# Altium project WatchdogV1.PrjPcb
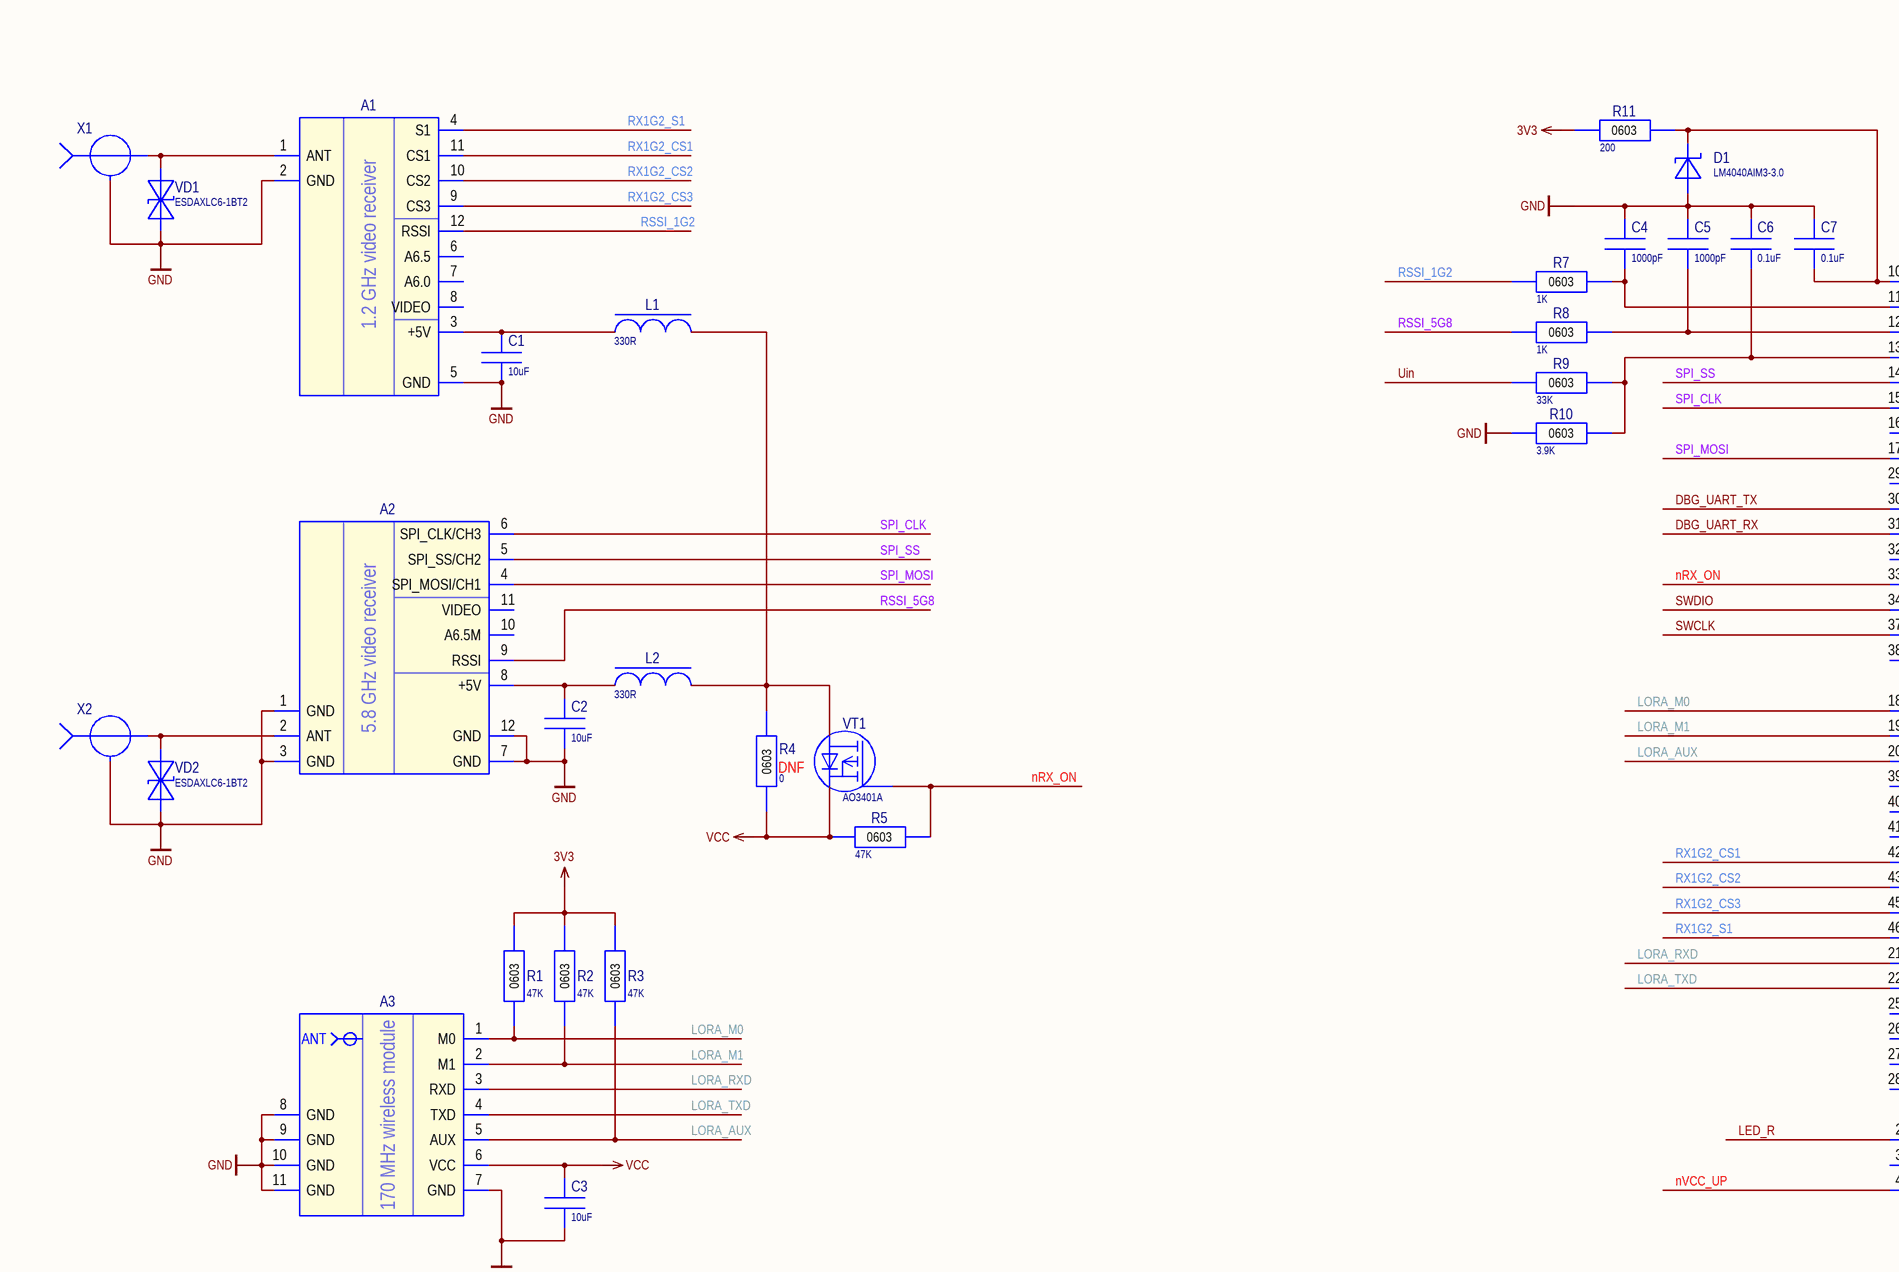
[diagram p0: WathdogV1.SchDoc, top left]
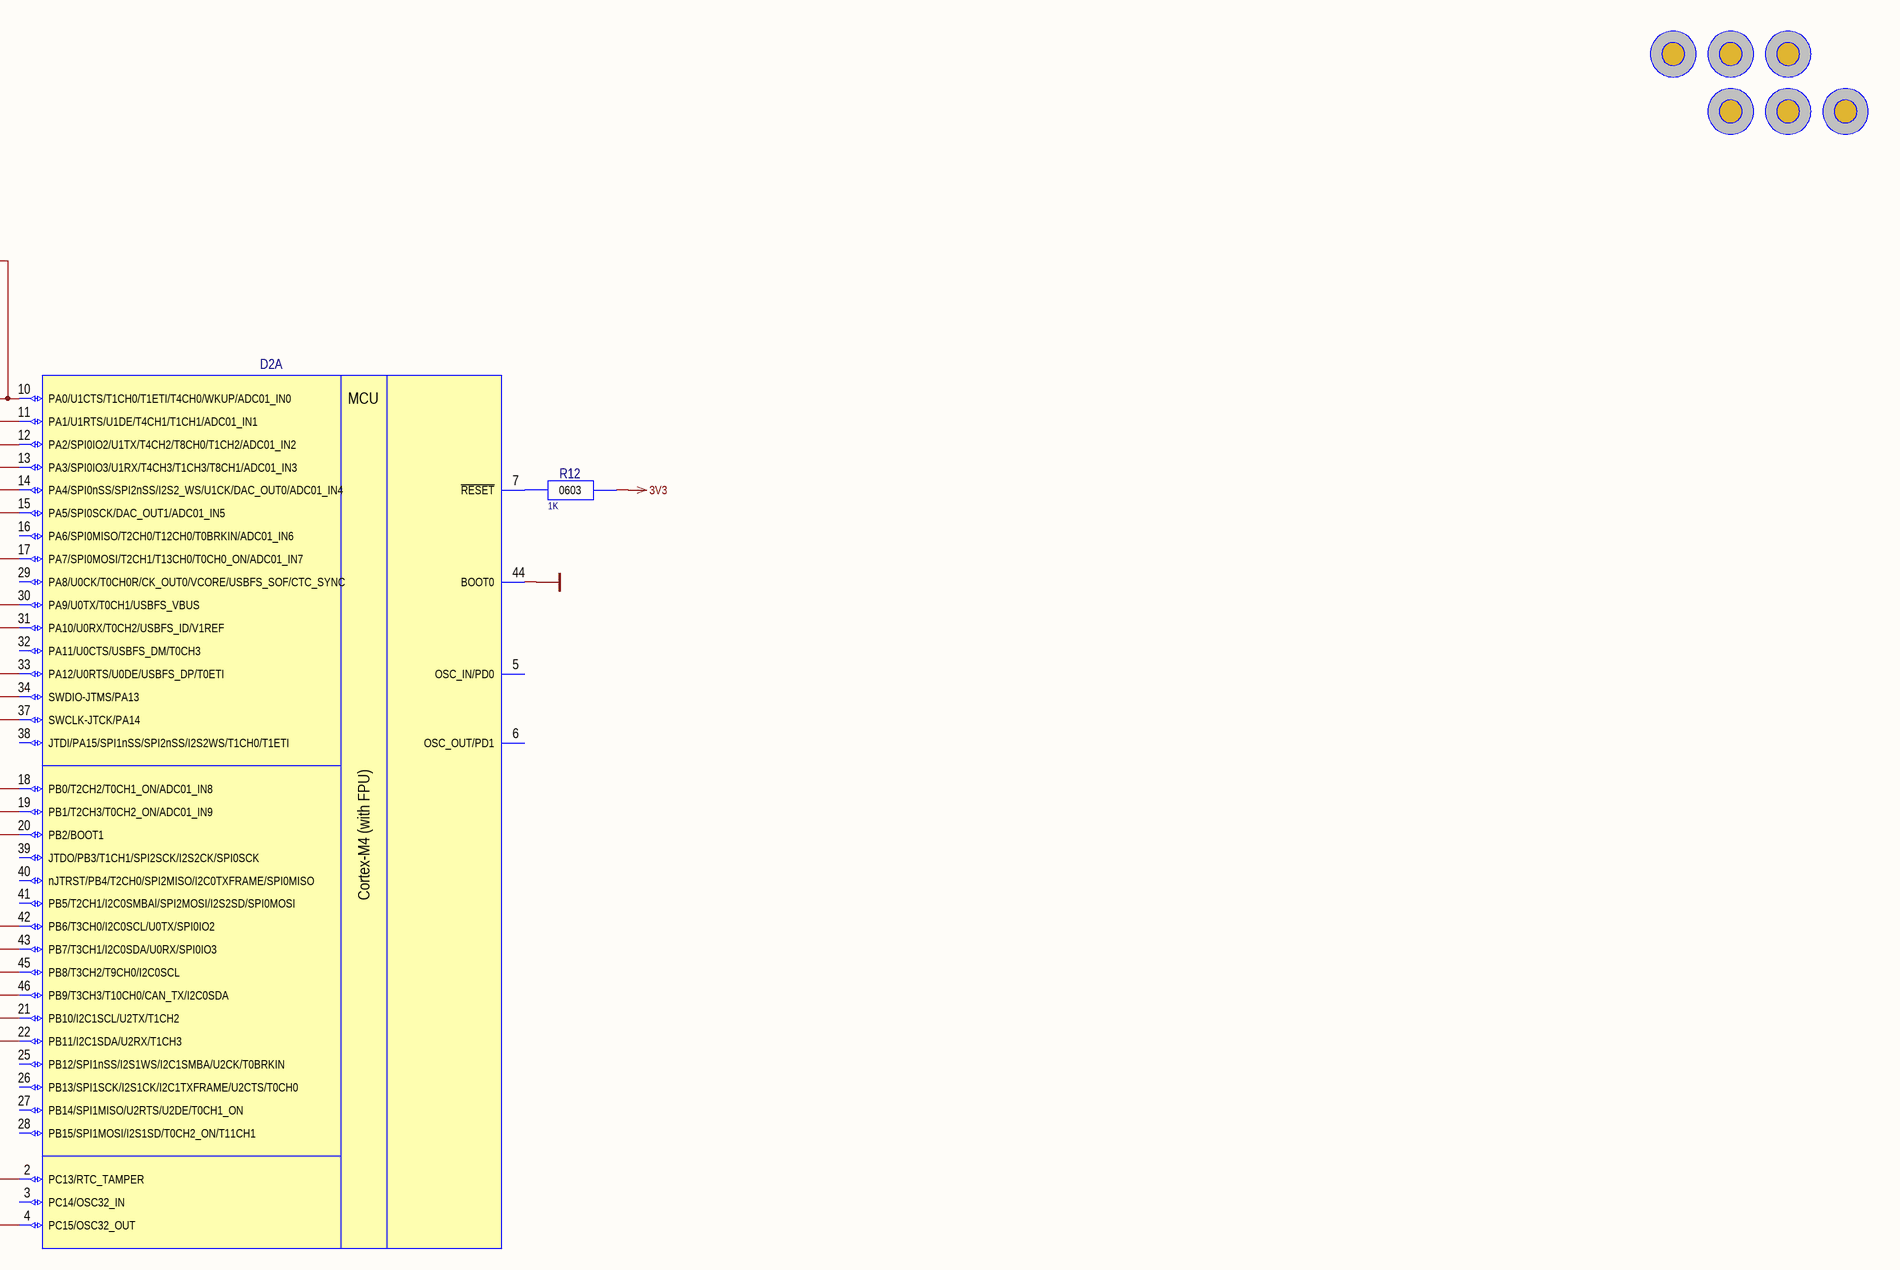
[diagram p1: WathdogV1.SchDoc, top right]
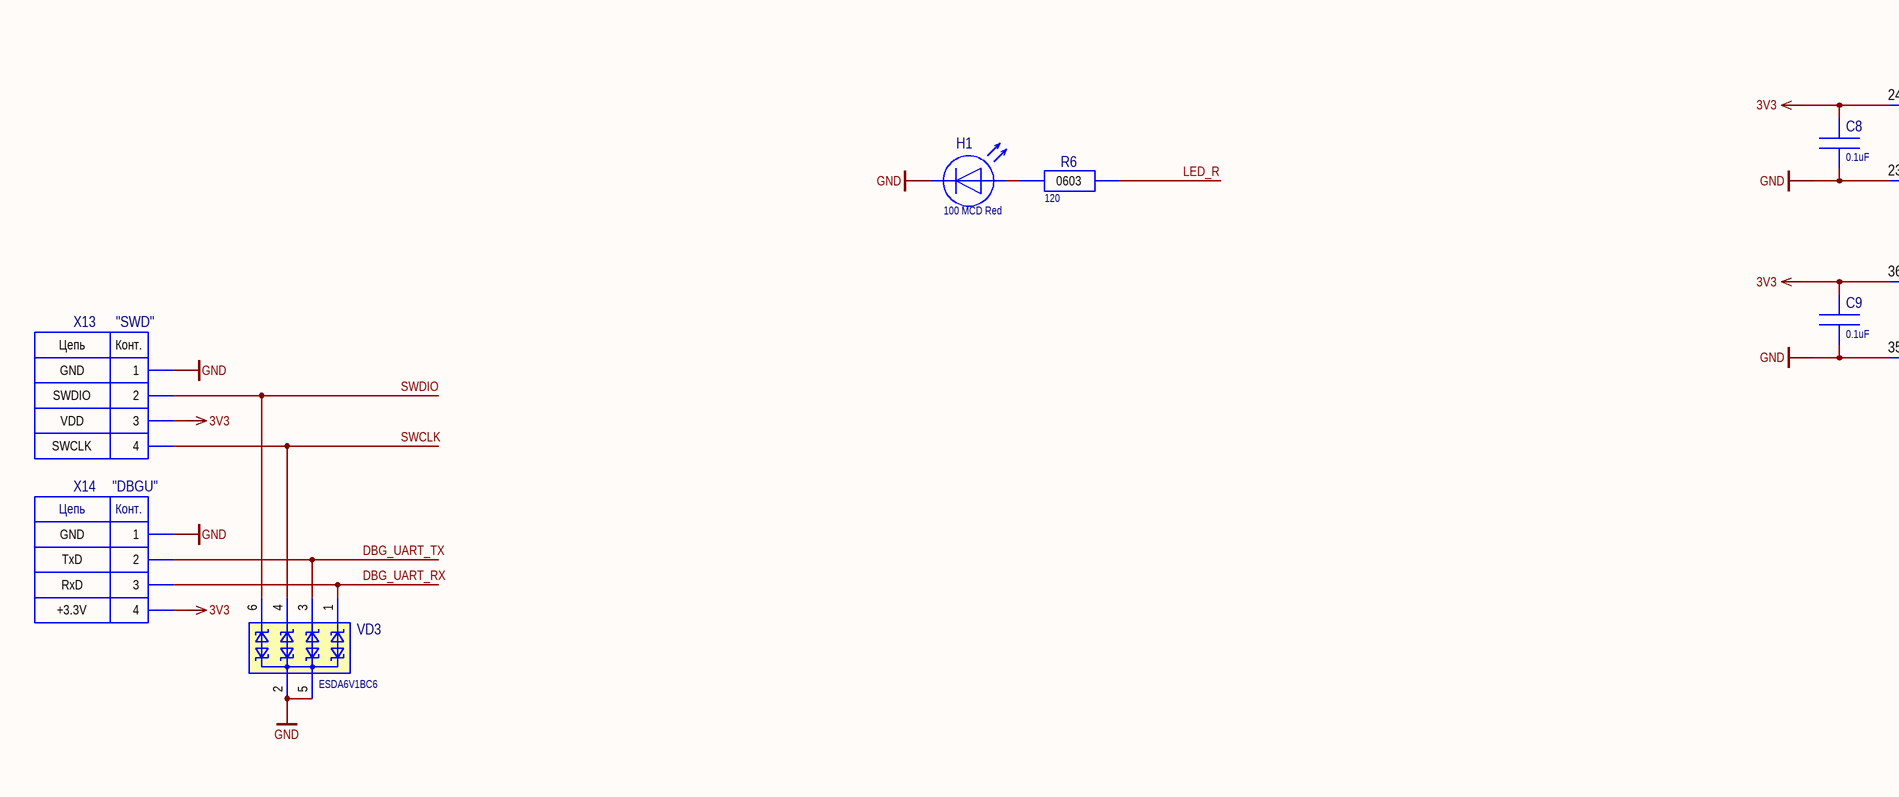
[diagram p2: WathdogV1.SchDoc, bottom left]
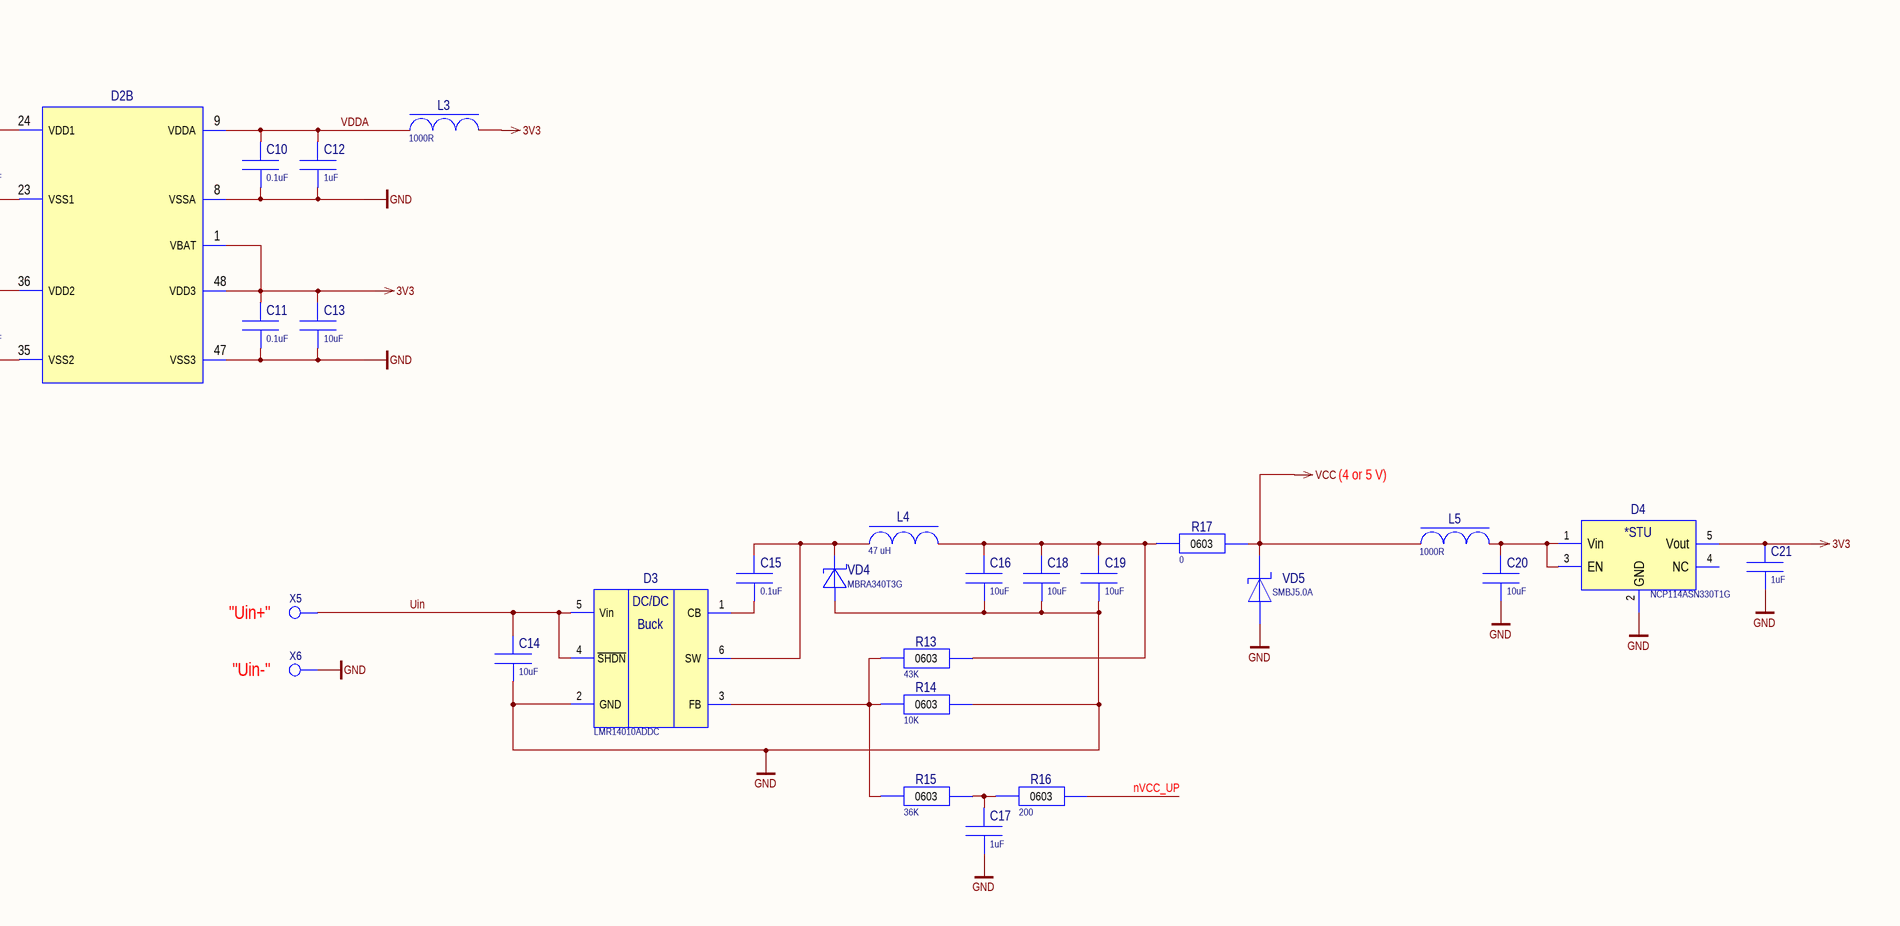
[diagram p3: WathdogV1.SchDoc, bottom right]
1 sheet, 69 parts. Net scope: global (net labels, ports and power ports of the same name join across sheets).
Board file: WatchdogV1.PcbDoc

## Sheet WathdogV1.SchDoc
size 840 x 594 mm; SheetNumber: 1; SheetTotal: 1; Разработал: КБИ

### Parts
A1  Receiver SM1370R  [SM1370R]  (value not drawn)
A2  Receiver RX5808  [RX5808]  (value not drawn)
A3  Wireless Module E32-170T30D  [E32-170T30D]  (value not drawn)
C1  value 10uF  [CC1206]  (hidden comment: Конденсатор керамический 1206-X7R-25V-10uF±10%)
C2  value 10uF  [CC1206]  (hidden comment: Конденсатор керамический 1206-X7R-25V-10uF±10%)
C3  value 10uF  [CC1206]  (hidden comment: Конденсатор керамический 1206-X7R-25V-10uF±10%)
C4  value 1000pF  [CC0603]  (hidden comment: Конденсатор керамический 0603-NP0-50V-1000pF±5%)
C5  value 1000pF  [CC0603]  (hidden comment: Конденсатор керамический 0603-NP0-50V-1000pF±5%)
C6  value 0.1uF  [CC0603]  (hidden comment: Конденсатор керамический 0603-X7R-50V-0.1uF±10%)
C7  value 0.1uF  [CC0603]  (hidden comment: Конденсатор керамический 0603-X7R-50V-0.1uF±10%)
C8  value 0.1uF  [CC0603]  (hidden comment: Конденсатор керамический 0603-X7R-50V-0.1uF±10%)
C9  value 0.1uF  [CC0603]  (hidden comment: Конденсатор керамический 0603-X7R-50V-0.1uF±10%)
C10  value 0.1uF  [CC0603]  (hidden comment: Конденсатор керамический 0603-X7R-50V-0.1uF±10%)
C11  value 0.1uF  [CC0603]  (hidden comment: Конденсатор керамический 0603-X7R-50V-0.1uF±10%)
C12  value 1uF  [CC0603]  (hidden comment: Конденсатор керамический 0603-X7R-16V-1uF±20%)
C13  value 10uF  [CC1206]  (hidden comment: Конденсатор керамический 1206-X7R-25V-10uF±10%)
C14  value 10uF  [CC1210]  (hidden comment: Конденсатор керамический 1210-X7R-63V-10uF±10%)
C15  value 0.1uF  [CC0603]  (hidden comment: Конденсатор керамический 0603-X7R-50V-0.1uF±10%)
C16  value 10uF  [CC1206]  (hidden comment: Конденсатор керамический 1206-X7R-25V-10uF±10%)
C17  value 1uF  [CC0603]  (hidden comment: Конденсатор керамический 0603-X7R-16V-1uF±20%)
C18  value 10uF  [CC1206]  (hidden comment: Конденсатор керамический 1206-X7R-25V-10uF±10%)
C19  value 10uF  [CC1206]  (hidden comment: Конденсатор керамический 1206-X7R-25V-10uF±10%)
C20  value 10uF  [CC1206]  (hidden comment: Конденсатор керамический 1206-X7R-25V-10uF±10%)
C21  value 1uF  [CC0603]  (hidden comment: Конденсатор керамический 0603-X7R-16V-1uF±20%)
D1  Микросхема LM4040AIM3-3.0  [SOT-23]  (value not drawn)
D2  Микросхема GD32E103CBT6  [LQFP48_7x7]  (value not drawn)  (parts A,B of 2)
D3  Микросхема LMR14010ADDC  [SOT-23-6]  (value not drawn)
D4  Name: NCP114ASN330T1G  [TSOP-5]  (hidden comment: Микросхема NCP114ASN330T1G)
H1  value 100 MCD Red  [LED0603_Red]  (hidden comment: Светодиод 0603-RED-[100-150]MCD)
L1  value 330R  [CL0603]  (hidden comment: Дроссель BLM18PG331SN1D)
L2  value 330R  [CL0603]  (hidden comment: Дроссель BLM18PG331SN1D)
L3  value 1000R  [CL0603]  (hidden comment: Дроссель BLM18AG102SN1D)
L4  value 47 uH  [SRR1260]  (hidden comment: Дроссель SRR1260-470M)
L5  value 1000R  [CL0603]  (hidden comment: Дроссель BLM18AG102SN1D)
R1  value 47K  [CR0603]  (hidden comment: Резистор 0603-0.1W-47K±5%)
R2  value 47K  [CR0603]  (hidden comment: Резистор 0603-0.1W-47K±5%)
R3  value 47K  [CR0603]  (hidden comment: Резистор 0603-0.1W-47K±5%)
R4  value 0  [CR0603]  (hidden comment: Резистор 0603-0.1W-0R)  (no BOM)
R5  value 47K  [CR0603]  (hidden comment: Резистор 0603-0.1W-47K±5%)
R6  value 120  [CR0603]  (hidden comment: Резистор 0603-0.1W-120R±5%)
R7  value 1K  [CR0603]  (hidden comment: Резистор 0603-0.1W-1K±5%)
R8  value 1K  [CR0603]  (hidden comment: Резистор 0603-0.1W-1K±5%)
R9  value 33K  [CR0603]  (hidden comment: Резистор 0603-0.1W-33K±1%)
R10  value 3.9K  [CR0603]  (hidden comment: Резистор 0603-0.1W-3.9K±1%)
R11  value 200  [CR0603]  (hidden comment: Резистор 0603-0.1W-200R±5%)
R12  value 1K  [CR0603]  (hidden comment: Резистор 0603-0.1W-1K±5%)
R13  value 43K  [CR0603]  (hidden comment: Резистор 0603-0.1W-43K±1%)
R14  value 10K  [CR0603]  (hidden comment: Резистор 0603-0.1W-10K±1%)
R15  value 36K  [CR0603]  (hidden comment: Резистор 0603-0.1W-36K±1%)
R16  value 200  [CR0603]  (hidden comment: Резистор 0603-0.1W-200R±5%)
R17  value 0  [CR0603]  (hidden comment: Резистор 0603-0.1W-0R)
RP1  Reper  [Reper-Min]  (value not drawn)  (no BOM)
RP2  Reper  [Reper-Min]  (value not drawn)  (no BOM)
RP3  Reper  [Reper-Min]  (value not drawn)  (no BOM)
RP4  Reper  [Reper-Min]  (value not drawn)  (no BOM)
RP5  Reper  [Reper-Min]  (value not drawn)  (no BOM)
RP6  Reper  [Reper-Min]  (value not drawn)  (no BOM)
VD1  Диод ESDAXLC6-1BT2  [ESDAXLC6-1BT2]  (value not drawn)
VD2  Диод ESDAXLC6-1BT2  [ESDAXLC6-1BT2]  (value not drawn)
VD3  Диодная сборка ESDA6V1BC6  [SOT-23-6]  (value not drawn)
VD4  Диод MBRA340T3G  [DO-214AC (SMA)]  (value not drawn)
VD5  Диод SMBJ5.0A  [DO-214AA]  (value not drawn)
VT1  Транзистор AO3401A  [SOT-23]  (value not drawn)
X1  Розетка KLS1-SMA060  [SMA_Edge]  (value not drawn)
X2  Розетка KLS1-SMA060  [SMA_Edge]  (value not drawn)
X3  Вилка PLS-4  [PLS-4]  (value not drawn)  (parts A,B,C,D of 4)
X4  Вилка PLS-4  [PLS-4]  (value not drawn)  (parts A,B,C,D of 4)
X5  Паяный контакт  [PD-6X4]  (value not drawn)  (no BOM)
X6  Паяный контакт  [PD-6X4]  (value not drawn)  (no BOM)

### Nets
3V3: C8.1 C9.1 C11.1 C13.1 C21.1 D2.1(VBAT) D2.24(VDD1) D2.36(VDD2) D2.48(VDD3) D4.5(Vout) L3.2 R1.2 R2.2 R3.2 R11.1 R12.2 X3.3 X4.4
GND: A1.2(GND) A1.5(GND) A2.1(GND) A2.3(GND) A2.7(GND) A2.12(GND) A3.7(GND) A3.8(GND) A3.9(GND) A3.10(GND) A3.11(GND) C1.2 C2.2 C3.2 C4.1 C5.1 C6.1 C7.1 C8.2 C9.2 C10.2 C11.2 C12.2 C13.2 C14.2 C16.2 C17.2 C18.2 C19.2 C20.2 C21.2 D1.2(+) D2.8(VSSA) D2.23(VSS1) D2.35(VSS2) D2.44(BOOT0) D2.47(VSS3) D3.2(GND) D4.2(GND) H1.2(-) R10.1 R14.2 VD1.1 VD2.1 VD3.2 VD3.5 VD4.1(+) VD5.A X1.2 X2.2 X3.1 X4.1 X6.1
VCC: A3.6(VCC) C3.1 L5.1 R4.1 R5.1 R17.2 VD5.K VT1.2(Source)
DBG_UART_RX: D2.31(PA10/U0RX/T0CH2/USBFS_ID/V1REF) VD3.1 X4.3
DBG_UART_TX: D2.30(PA9/U0TX/T0CH1/USBFS_VBUS) VD3.3 X4.2
LED_R: D2.2(PC13/RTC_TAMPER) R6.2
LORA_AUX: A3.5(AUX) D2.20(PB2/BOOT1) R3.1
LORA_M0: A3.1(M0) D2.18(PB0/T2CH2/T0CH1_ON/ADC01_IN8) R1.1
LORA_M1: A3.2(M1) D2.19(PB1/T2CH3/T0CH2_ON/ADC01_IN9) R2.1
LORA_RXD: A3.3(RXD) D2.21(PB10/I2C1SCL/U2TX/T1CH2)
LORA_TXD: A3.4(TXD) D2.22(PB11/I2C1SDA/U2RX/T1CH3)
nRX_ON: D2.33(PA12/U0RTS/U0DE/USBFS_DP/T0ETI) R5.2 VT1.1(Gate)
nVCC_UP: D2.4(PC15/OSC32_OUT) R16.2
RSSI_1G2: A1.12(RSSI) R7.1
RSSI_5G8: A2.9(RSSI) R8.1
RX1G2_CS1: A1.11(CS1) D2.42(PB6/T3CH0/I2C0SCL/U0TX/SPI0IO2)
RX1G2_CS2: A1.10(CS2) D2.43(PB7/T3CH1/I2C0SDA/U0RX/SPI0IO3)
RX1G2_CS3: A1.9(CS3) D2.45(PB8/T3CH2/T9CH0/I2C0SCL)
RX1G2_S1: A1.4(S1) D2.46(PB9/T3CH3/T10CH0/CAN_TX/I2C0SDA)
SPI_CLK: A2.6(SPI_CLK/CH3) D2.15(PA5/SPI0SCK/DAC_OUT1/ADC01_IN5)
SPI_MOSI: A2.4(SPI_MOSI/CH1) D2.17(PA7/SPI0MOSI/T2CH1/T13CH0/T0CH0_ON/ADC01_IN7)
SPI_SS: A2.5(SPI_SS/CH2) D2.14(PA4/SPI0nSS/SPI2nSS/I2S2_WS/U1CK/DAC_OUT0/ADC01_IN4)
SWCLK: D2.37(SWCLK-JTCK/PA14) VD3.4 X3.4
SWDIO: D2.34(SWDIO-JTMS/PA13) VD3.6 X3.2
Uin: C14.1 D3.4(~{SHDN}) D3.5(Vin) R9.1 X5.1
VDDA: C10.1 C12.1 D2.9(VDDA) L3.1
NetA1_1: A1.1(ANT) VD1.2 X1.1
NetA1_3: A1.3(+5V) C1.1 L1.1
NetA2_2: A2.2(ANT) VD2.2 X2.1
NetA2_8: A2.8(+5V) C2.1 L2.1
NetC4_2: C4.2 D2.11(PA1/U1RTS/U1DE/T4CH1/T1CH1/ADC01_IN1) R7.2
NetC5_2: C5.2 D2.12(PA2/SPI0IO2/U1TX/T4CH2/T8CH0/T1CH2/ADC01_IN2) R8.2
NetC6_2: C6.2 D2.13(PA3/SPI0IO3/U1RX/T4CH3/T1CH3/T8CH1/ADC01_IN3) R9.2 R10.2
NetC7_2: C7.2 D1.1(-) D2.10(PA0/U1CTS/T1CH0/T1ETI/T4CH0/WKUP/ADC01_IN0) R11.2
NetC15_1: C15.1 D3.6(SW) L4.1 VD4.2(-)
NetC15_2: C15.2 D3.1(CB)
NetC16_1: C16.1 C18.1 C19.1 L4.2 R13.2 R17.1
NetC17_1: C17.1 R15.2 R16.1
NetC20_1: C20.1 D4.1(Vin) D4.3(EN) L5.2
NetD2_7: D2.7(~{RESET}) R12.1
NetD3_3: D3.3(FB) R13.1 R14.1 R15.1
NetH1_1: H1.1(+) R6.1
NetL1_2: L1.2 L2.2 R4.2 VT1.3(Drain)

Not connected (* = marked no-connect by the designer): A1 6(A6.5) 7(A6.0) 8(VIDEO); A2 10(A6.5M) 11(VIDEO); D2 3(PC14/OSC32_IN) 5(OSC_IN/PD0) 6(OSC_OUT/PD1) 16(PA6/SPI0MISO/T2CH0/T12CH0/T0BRKIN/ADC01_IN6) 25(PB12/SPI1nSS/I2S1WS/I2C1SMBA/U2CK/T0BRKIN) 26(PB13/SPI1SCK/I2S1CK/I2C1TXFRAME/U2CTS/T0CH0) 27(PB14/SPI1MISO/U2RTS/U2DE/T0CH1_ON) 28(PB15/SPI1MOSI/I2S1SD/T0CH2_ON/T11CH1) 29(PA8/U0CK/T0CH0R/CK_OUT0/VCORE/USBFS_SOF/CTC_SYNC) 32(PA11/U0CTS/USBFS_DM/T0CH3) 38(JTDI/PA15/SPI1nSS/SPI2nSS/I2S2WS/T1CH0/T1ETI) 39(JTDO/PB3/T1CH1/SPI2SCK/I2S2CK/SPI0SCK) 40(nJTRST/PB4/T2CH0/SPI2MISO/I2C0TXFRAME/SPI0MISO) 41(PB5/T2CH1/I2C0SMBAl/SPI2MOSI/I2S2SD/SPI0MOSI); D4 4(NC)

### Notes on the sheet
- (near R4) DNF
- Цепь
- X13
- (near X3) Конт.
- (near X3) "SWD"
- GND
- VDD
- SWDIO
- SWCLK
- (4 or 5 V)
- X14
- (near X4) Конт.
- "DBGU"
- TxD
- RxD
- +3.3V
- (near X5) "Uin+"
- (near X6) "Uin-"

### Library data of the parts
A1 = SM1370R: Аналоговый видеоприемник 1,2 ГГц
A2 = RX5808: Аналоговый видеоприемник 5,8 ГГц
A3 = E32-170T30D: Приемопередатчик 170 МГц
C1-C3 C13 C16 C18-C20 = CC1206-X7R-25V-10uF±10%: Конденсатор керамический SMD; Manufacturer: Murata; Name: GRM31CR71E106KA12L
C4 C5 = CC0603-NP0-50V-1000pF±5%: Конденсатор керамический SMD; Manufacturer: Murata; Name: GRM1885C1H102J
C6-C11 C15 = CC0603-X7R-50V-0.1uF±10%: Конденсатор керамический SMD; Manufacturer: Samsung; Name: CL10B104KB8NNNC
C12 C17 C21 = CC0603-X7R-16V-1uF±20%: Конденсатор керамический SMD; Manufacturer: Samsung; Name: CL10B105MO8NNWC
C14 = CC1210-X7R-50V-10uF±20%: Конденсатор керамический SMD; Manufacturer: Murata; Name: GRM32ER71J106KA12L
D1 = LM4040AIM3-3.0: ИОН 3.0V±0.1%; -40...+85C; Manufacturer: TI
D2 = GD32E103Cxxx: ARM Cortrex-M4; Manufacturer: GigaDevice; SubType: Микроконтроллер; Param: ARM Cortex-M4; 120 МГц
D3 = LMR14010ADDC: DC/DC понижающий; Manufacturer: TI; Subtype: понижающий DC/DC преобразователь; Param: Vin: 4...40V; Iout 1A; 0.7 MHz
D4 = NCP114ASN330T: LDO, 3.3V, 300mA, TSOP-5, -40...+85C; High Power Supply Ripple Rejection: 75 dB at 1 kHz; Manufacturer: ON; Subtype: Линейный стабилизатор напряжения; Param: 3.3V;  300mA
H1 = LED-0603-RED: 0603 SMD-светодиод красный; Manufacturer: Kingbright; SubType: SMD; Name: KPT-1608SURC
L1 L2 = BLM18PG331SN1D: Чип-индуктивность подавления ЭМП. Типоразмер 0603; Manufacturer: Murata; SubType: подавления EMI; Param: 0603-1A-0.15R-330R-100MHz
L3 L5 = BLM18AG102SN1D: Чип-индуктивность подавления ЭМП. Типоразмер 0603; Manufacturer: Murata; SubType: подавления EMI; Param: 0603-400mA-0.5R-1K±25%-100MHz
L4 = SRR1260: SMD fix. ind.; 12.5x12.5x6.0mm; Manufacturer: Bourns
R1-R3 R5 = CR0603-0.1W-47K±5%: Чип резистор; Manufacturer: Yageo; Name: RC0603JR-0747KL; Voltage: 75V
R4 R17 = CR0603-0.1W-0R: Чип резистор; Manufacturer: Yageo; Name: RC0603JR-070RL; Voltage: 75V
R6 = CR0603-0.1W-120R±5%: Чип резистор; Manufacturer: Yageo; Name: RC0603JR-07120RL; Voltage: 75V
R7 R8 R12 = CR0603-0.1W-1K±5%: Чип резистор; Manufacturer: Yageo; Name: RC0603JR-071KL; Voltage: 75V
R9 = CR0603-0.1W-33K±1%: Чип резистор; Manufacturer: Yageo; Name: RC0603FR-0733KL; Voltage: 75V
R10 = CR0603-0.1W-3.9K±1%: Чип резистор; Manufacturer: Yageo; Name: RC0603FR-073K9L; Voltage: 75V
R11 R16 = CR0603-0.1W-200R±5%: Чип резистор; Manufacturer: Yageo; Name: RC0603JR-07200RL; Voltage: 75V
R13 = CR0603-0.1W-43K±1%: Чип резистор; Manufacturer: Yageo; Name: RC0603FR-0743KL; Voltage: 75V
R14 = CR0603-0.1W-10K±1%: Чип резистор; Manufacturer: Yageo; Name: RC0603FR-0710KL; Voltage: 75V
R15 = CR0603-0.1W-36K±1%: Чип резистор; Manufacturer: Yageo; Name: RC0603FR-0736KL; Voltage: 75V
VD1 VD2 = ESDAXLC6-1BT2: Single line ESD protection for high speed lines in 0402; Manufacturer: ST; SubType: TVS
VD3 = ESDA6V1BC6: 4 TVS-диода с общей шиной; Manufacturer: ST; SubType: TVS
VD4 = MBRA340T3G: Диод шотки I=3А V=40В; Manufacturer: ON; SubType: шоттки
VD5 = SMBJ5.0A: TVS-диод (супрессор); 5V; Vbr 6.4V; 600W; Manufacturer: Vishay; Param: Uwork 5V; Ubr 6.4V;  600W
VT1 = AO3401A: P-channel MOSFET; 30V; 4.2A; -55...+150C; Manufacturer: UMW; Subtype: P-канальный MOSFET
X1 X2 = KLS1-SMA060: SMA розетка монтаж с торца платы; Manufacturer: KLS
X3 X4 = PLS-4_TABLE: Вилка на плату однорядная прямая

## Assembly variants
Main: not fitted R4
